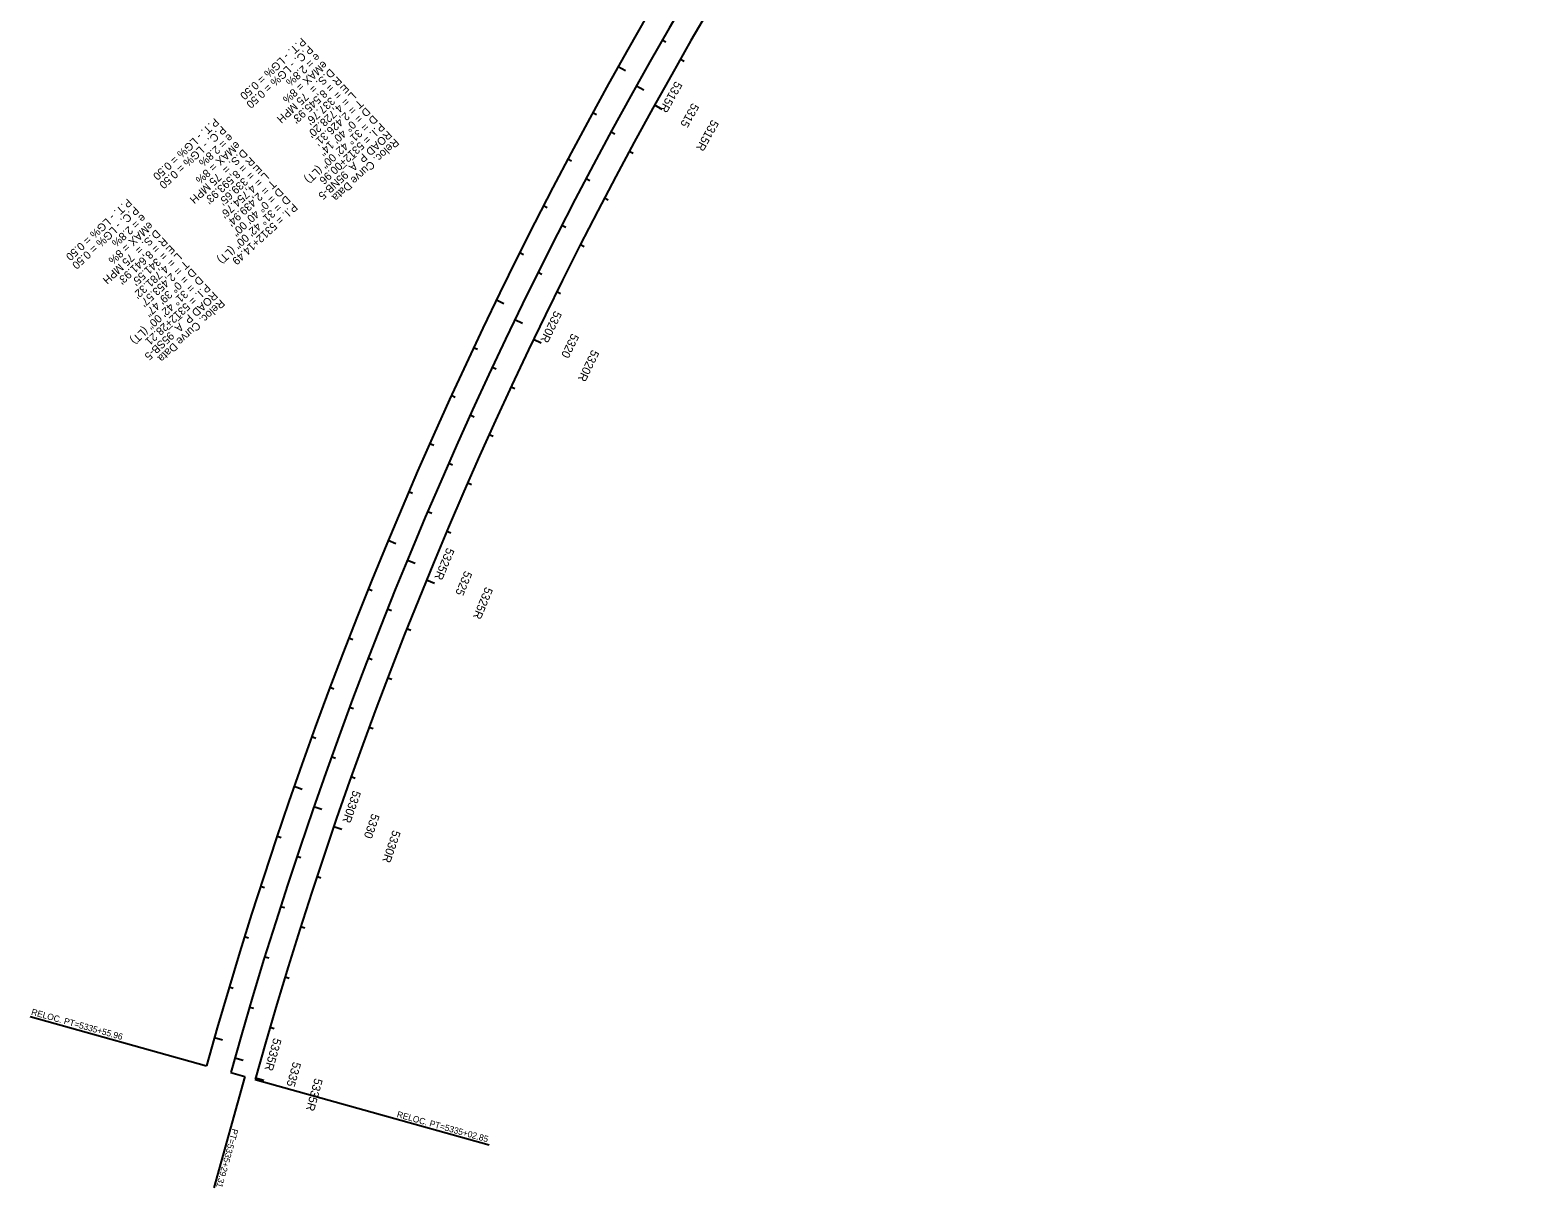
# Model space of a CAD drawing. Extents: x 2160876 to 2175625, y 601634 to 617693.
# Drawn here: x 2160876 to 2163737, y 601634 to 603831 of the extents above; entities that cross this region are included whole.
import ezdxf

# ---------------------------------------------------------------- set-up
doc = ezdxf.new("R2010")
doc.units = 0
for name, color, linetype in [('RD_HC_Cl', 7, 'Continuous'), ('RD_HC_CL_Rel', 7, 'Continuous'), ('RD_HC_Data', 7, 'Continuous'), ('RD_HC_Data_Rel', 7, 'Continuous'), ('RD_HC_Data_Tic', 7, 'Continuous'), ('RD_HC_Data_Tic_Rel', 7, 'Continuous'), ('RD_HC_TX_Rel_Sta50', 7, 'Continuous'), ('RD_HC_TX_Sta50', 7, 'Continuous')]:
    doc.layers.add(name, color=color, linetype=linetype)

msp = doc.modelspace()

# ---------------------------------------------------------------- linework, layer by layer
at = {"layer": 'RD_HC_Cl'}
msp.add_arc((2169535, 599544.7), 8593.9, 132.71947, 164.41949, dxfattribs=at)
at = {"layer": 'RD_HC_CL_Rel'}
for radius in [8641.9, 8545.9]:
    msp.add_arc((2169535, 599544.7), radius, 132.71947, 164.41949, dxfattribs=at)
at = {"layer": 'RD_HC_Data'}
for p, q in [((2161283.6, 601845.5), (2161224.7, 601634.4)), ((2161256.9, 601853), (2161283.6, 601845.5))]:
    msp.add_line(p, q, dxfattribs=at)
at = {"layer": 'RD_HC_Data_Rel'}
for p, q in [((2160876.1, 601959.2), (2161210.6, 601865.9)), ((2161303.1, 601840.1), (2161747.5, 601716.2))]:
    msp.add_line(p, q, dxfattribs=at)
at = {"layer": 'RD_HC_Data_Tic'}
for p, q in [((2162075.8, 603812.7), (2162082.7, 603808.7)), ((2162026.6, 603725.6), (2162040.6, 603717.8)), ((2161978.5, 603637.9), (2161985.5, 603634.1)), ((2161931.3, 603549.7), (2161938.4, 603546)), ((2161885.3, 603461), (2161892.4, 603457.3)), ((2161840.2, 603371.7), (2161847.4, 603368.1)), ((2161796.2, 603281.9), (2161810.6, 603274.9)), ((2161753.2, 603191.6), (2161760.5, 603188.2)), ((2161711.3, 603100.8), (2161718.6, 603097.5)), ((2161670.5, 603009.5), (2161677.8, 603006.3)), ((2161630.7, 602917.8), (2161638.1, 602914.6)), ((2161592, 602825.6), (2161606.8, 602819.5)), ((2161554.3, 602732.9), (2161561.8, 602730)), ((2161517.8, 602639.9), (2161525.2, 602637)), ((2161482.3, 602546.4), (2161489.8, 602543.6)), ((2161447.9, 602452.5), (2161455.5, 602449.7)), ((2161414.6, 602358.2), (2161429.8, 602352.9)), ((2161382.5, 602263.5), (2161390, 602260.9)), ((2161351.4, 602168.4), (2161359, 602166)), ((2161321.4, 602073), (2161329, 602070.7)), ((2161292.5, 601977.3), (2161300.2, 601975)), ((2161264.8, 601881.2), (2161280.2, 601876.9))]:
    msp.add_line(p, q, dxfattribs=at)
at = {"layer": 'RD_HC_Data_Tic_Rel'}
for p, q in [((2161992.1, 603762.3), (2162006.1, 603754.5)), ((2162110.2, 603776.2), (2162117.1, 603772.2)), ((2161943.8, 603674.7), (2161950.9, 603670.9)), ((2162061.2, 603689), (2162075.2, 603681.2)), ((2161896.5, 603586.6), (2161903.6, 603582.9)), ((2162013.2, 603601.3), (2162020.2, 603597.5)), ((2161850.3, 603498), (2161857.4, 603494.3)), ((2161966.3, 603513), (2161973.3, 603509.2)), ((2161920.3, 603424.1), (2161927.5, 603420.5)), ((2161805.1, 603408.8), (2161812.2, 603405.2)), ((2161875.5, 603334.8), (2161882.6, 603331.2)), ((2161760.9, 603319.1), (2161775.3, 603312.1)), ((2161831.6, 603244.9), (2161846.1, 603237.9)), ((2161717.7, 603228.9), (2161724.9, 603225.4)), ((2161788.9, 603154.5), (2161796.1, 603151.1)), ((2161675.6, 603138.2), (2161682.9, 603134.8)), ((2161634.5, 603047), (2161641.9, 603043.7)), ((2161747.2, 603063.6), (2161754.5, 603060.3)), ((2161594.6, 602955.3), (2161601.9, 602952.2)), ((2161706.5, 602972.2), (2161713.9, 602969)), ((2161667, 602880.4), (2161674.3, 602877.3)), ((2161555.6, 602863.2), (2161570.4, 602857.1)), ((2161628.5, 602788.1), (2161643.3, 602782)), ((2161517.8, 602770.7), (2161525.2, 602767.7)), ((2161591, 602695.4), (2161598.5, 602692.4)), ((2161481, 602677.7), (2161488.4, 602674.8)), ((2161445.2, 602584.3), (2161452.7, 602581.5)), ((2161554.7, 602602.2), (2161562.2, 602599.3)), ((2161519.5, 602508.6), (2161527, 602505.8)), ((2161410.6, 602490.5), (2161418.1, 602487.7)), ((2161485.4, 602414.6), (2161492.9, 602411.9)), ((2161377.1, 602396.2), (2161392.2, 602391)), ((2161344.6, 602301.7), (2161352.2, 602299.1)), ((2161452.3, 602320.2), (2161467.5, 602315)), ((2161420.4, 602225.5), (2161428, 602222.9)), ((2161313.3, 602206.7), (2161320.9, 602204.2)), ((2161389.6, 602130.3), (2161397.2, 602127.9)), ((2161283, 602111.4), (2161290.7, 602109)), ((2161253.9, 602015.7), (2161261.5, 602013.4)), ((2161359.9, 602034.8), (2161367.6, 602032.5)), ((2161331.3, 601939), (2161339, 601936.8)), ((2161225.8, 601919.7), (2161241.2, 601915.3)), ((2161303.9, 601842.8), (2161319.3, 601838.5))]:
    msp.add_line(p, q, dxfattribs=at)

# ---------------------------------------------------------------- texts
at = {"layer": 'RD_HC_Data'}
for s, height, rotation, p in [('P.T. - LG% = 0.50', 15, 222.7195, (2161226.2, 603665.1)), ('P.C. - LG% = 0.50', 15, 222.7195, (2161239.7, 603650.4)), ('eMAX = 8%', 15, 222.7195, (2161266.9, 603621)), ('e = 2.8%', 15, 222.7195, (2161253.3, 603635.7)), ('D.S. =  75 MPH', 15, 222.7195, (2161280.4, 603606.3)), ("R = 8,593.93'", 15, 222.7195, (2161294, 603591.6)), ("E = 339.65'", 15, 222.7195, (2161307.6, 603576.9)), ("L = 4,754.76'", 15, 222.7195, (2161321.1, 603562.2)), ("T = 2,439.94'", 15, 222.7195, (2161334.7, 603547.5)), ('D = 0° 40\' 00"', 15, 222.7195, (2161348.3, 603532.8)), ('    = 31° 42\' 00" (LT)', 15, 222.7195, (2161361.8, 603518.2)), ('P.I. = 5312+14.49', 15, 222.7195, (2161375.4, 603503.5)), ('D', 15, 222.7195, (2161361.8, 603518.2)), ('PT=5335+29.31', 12, 254.4195, (2161259.8, 601747.6))]:
    msp.add_text(s, height=height, rotation=rotation, dxfattribs=at).set_placement(p)
at = {"layer": 'RD_HC_Data_Rel'}
for s, height, rotation, p in [('P.T. - LG% = 0.50', 15, 222.7195, (2161391.5, 603817.7)), ('P.C. - LG% = 0.50', 15, 222.7195, (2161405, 603803)), ('e = 2.8%', 15, 222.7195, (2161418.6, 603788.3)), ('D.S. =  75 MPH', 15, 222.7195, (2161445.7, 603759)), ('eMAX = 8%', 15, 222.7195, (2161432.2, 603773.7)), ("R = 8,545.93'", 15, 222.7195, (2161459.3, 603744.3)), ("E = 337.76'", 15, 222.7195, (2161472.9, 603729.6)), ("L = 4,728.20'", 15, 222.7195, (2161486.4, 603714.9)), ("T = 2,426.31'", 15, 222.7195, (2161500, 603700.2)), ('D = 0° 40\' 14"', 15, 222.7195, (2161513.6, 603685.5)), ('D', 15, 222.7195, (2161527.2, 603670.8)), ('    = 31° 42\' 00" (LT)', 15, 222.7195, (2161527.2, 603670.8)), ('ROAD P_A_95NB-5', 15, 222.7195, (2161554.3, 603641.4)), ('P.I. = 5312+00.96', 15, 222.7195, (2161540.7, 603656.1)), ('Reloc. Curve Data', 15, 222.7195, (2161567.9, 603626.7)), ('P.T. - LG% = 0.50', 15, 222.7195, (2161060.9, 603512.4)), ('P.C. - LG% = 0.50', 15, 222.7195, (2161074.4, 603497.8)), ('e = 2.8%', 15, 222.7195, (2161088, 603483.1)), ('D.S. =  75 MPH', 15, 222.7195, (2161115.1, 603453.7)), ('eMAX = 8%', 15, 222.7195, (2161101.6, 603468.4)), ("R = 8,641.93'", 15, 222.7195, (2161128.7, 603439)), ("E = 341.55'", 15, 222.7195, (2161142.3, 603424.3)), ("L = 4,781.32'", 15, 222.7195, (2161155.8, 603409.6)), ("T = 2,453.57'", 15, 222.7195, (2161169.4, 603394.9)), ('D = 0° 39\' 47"', 15, 222.7195, (2161183, 603380.2)), ('D', 15, 222.7195, (2161196.5, 603365.5)), ('    = 31° 42\' 00" (LT)', 15, 222.7195, (2161196.5, 603365.5)), ('P.I. = 5312+28.21', 15, 222.7195, (2161210.1, 603350.8)), ('ROAD P_A_95SB-5', 15, 222.7195, (2161223.7, 603336.1)), ('Reloc. Curve Data', 15, 222.7195, (2161237.2, 603321.4)), ('RELOC. PT=5335+55.96', 12, 344.4195, (2160877.2, 601963)), ('RELOC. PT=5335+02.85', 12, 344.4195, (2161571, 601768.7))]:
    msp.add_text(s, height=height, rotation=rotation, dxfattribs=at).set_placement(p)
at = {"layer": 'RD_HC_TX_Rel_Sta50'}
for s, rotation, p in [('5315R', 240.7885, (2162100.7, 603735.2)), ('5315R', 240.9915, (2162169.9, 603662.3)), ('5320R', 244.1035, (2161871.4, 603299.5)), ('5320R', 244.3437, (2161942.3, 603225.8)), ('5325R', 247.4185, (2161667.1, 602850.1)), ('5325R', 247.6959, (2161740, 602775.6)), ('5330R', 250.7335, (2161489.2, 602389.6)), ('5330R', 251.0482, (2161564.5, 602314.2)), ('5335R', 254.0485, (2161338.1, 601919.6)), ('5335R', 254.4004, (2161416.2, 601843.4))]:
    msp.add_text(s, height=16, rotation=rotation, dxfattribs=at).set_placement(p)
at = {"layer": 'RD_HC_TX_Sta50'}
for s, rotation, p in [('5315', 240.8901, (2162132.5, 603693.7)), ('5320', 244.2236, (2161904, 603256.7)), ('5325', 247.5571, (2161700.8, 602806.2)), ('5330', 250.8906, (2161524.6, 602345.6)), ('5335', 254.2241, (2161375.2, 601874.6))]:
    msp.add_text(s, height=16, rotation=rotation, dxfattribs=at).set_placement(p)

doc.saveas('drawing.dxf')
